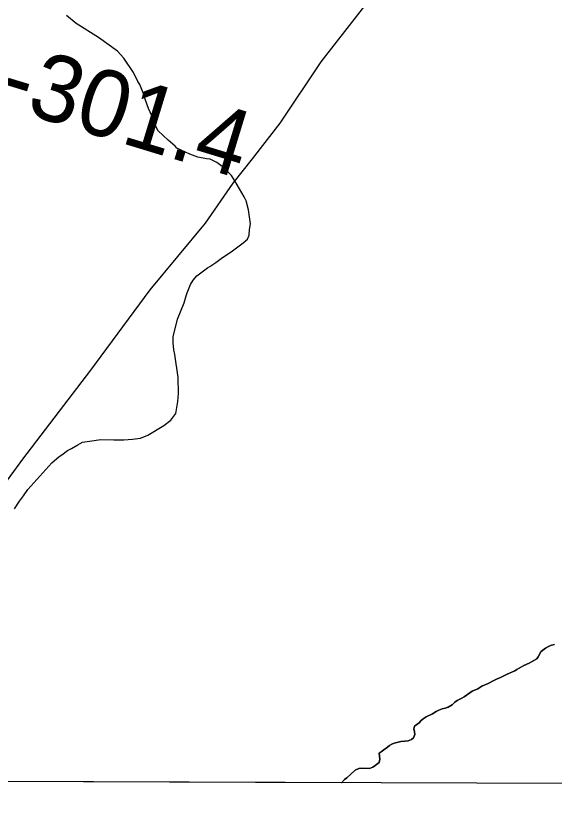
# Model space of a CAD drawing. Extents: x 3146026 to 3183936, y 897894 to 923344.
# Drawn here: x 3175467 to 3176138, y 903274 to 904248 of the extents above; entities that cross this region are included whole.
import ezdxf

# ---------------------------------------------------------------- set-up
doc = ezdxf.new("R2010")
doc.units = 0
for name, color, linetype in [('V-GRID-FRAM', 7, 'Continuous'), ('V-RIVR-RANG-IDEN', 7, 'Continuous'), ('V-ROAD-CNTR', 7, 'Continuous'), ('V-SITE-VEGE', 7, 'Continuous'), ('V-TOPO-SHOR', 7, 'Continuous')]:
    doc.layers.add(name, color=color, linetype=linetype)

msp = doc.modelspace()

# ---------------------------------------------------------------- linework, layer by layer
at = {"layer": 'V-GRID-FRAM'}
msp.add_lwpolyline([(3150311.93, 921563.12), (3181636.98, 921462.88), (3181586.71, 903274.26), (3150245.8, 903374.55), (3150311.93, 921563.12)], dxfattribs=at)
at = {"layer": 'V-ROAD-CNTR'}
msp.add_lwpolyline([(3176191.1, 904677.37), (3176143.65, 904608.46), (3176077.14, 904509.71), (3176012.07, 904414.15), (3175944.13, 904315.76), (3175847.16, 904190.43), (3175795.74, 904114.06), (3175761.27, 904069.68), (3175737.21, 904039.51), (3175703.06, 903989.78), (3175634.13, 903906.72), (3175560.12, 903806.59), (3175475.36, 903695.45), (3175374.76, 903558.74)], dxfattribs=at)
at = {"layer": 'V-SITE-VEGE'}
for p, q in [((3175542.06, 904238.36), (3175530.08, 904248.14)), ((3175570.2, 904221.07), (3175542.06, 904238.36)), ((3175593.71, 904203.82), (3175570.2, 904221.07)), ((3175601.53, 904194.98), (3175593.71, 904203.82)), ((3175613.47, 904177.32), (3175601.53, 904194.98)), ((3175618.97, 904166.18), (3175613.47, 904177.32)), ((3175621.72, 904162.46), (3175618.97, 904166.18)), ((3175625.83, 904151.79), (3175621.72, 904162.46)), ((3175628.56, 904142.98), (3175625.83, 904151.79)), ((3175632.2, 904132.31), (3175628.56, 904142.98)), ((3175636.31, 904123.5), (3175632.2, 904132.31)), ((3175642.25, 904108.19), (3175636.31, 904123.5)), ((3175644.54, 904104.47), (3175642.25, 904108.19)), ((3175656.98, 904092.83), (3175644.54, 904104.47)), ((3175665.73, 904085.37), (3175656.98, 904092.83)), ((3175667.57, 904083.05), (3175665.73, 904085.37)), ((3175683.73, 904075.55), (3175667.57, 904083.05)), ((3175693.89, 904071.8), (3175683.73, 904075.55)), ((3175704.53, 904069.88), (3175693.89, 904071.8)), ((3175709.15, 904069.39), (3175704.53, 904069.88)), ((3175717.46, 904065.18), (3175709.15, 904069.39)), ((3175723.91, 904060.05), (3175717.46, 904065.18)), ((3175735.89, 904048.88), (3175723.91, 904060.05)), ((3175740.02, 904042.37), (3175735.89, 904048.88)), ((3175751.48, 904022.4), (3175740.02, 904042.37)), ((3175753.77, 904017.3), (3175751.48, 904022.4)), ((3175756.94, 904006.17), (3175753.77, 904017.3)), ((3175759.16, 903988.57), (3175756.94, 904006.17)), ((3175757.69, 903974.69), (3175758.2, 903981.63)), ((3175758.2, 903981.63), (3175759.16, 903988.57)), ((3175755.81, 903969.61), (3175757.69, 903974.69)), ((3175735.36, 903953.98), (3175750.23, 903965.01)), ((3175750.23, 903965.01), (3175755.81, 903969.61)), ((3175724.67, 903946.64), (3175735.36, 903953.98)), ((3175716.31, 903940.67), (3175724.67, 903946.64)), ((3175692.61, 903924.13), (3175705.62, 903933.78)), ((3175705.62, 903933.78), (3175708.87, 903935.62)), ((3175708.87, 903935.62), (3175716.31, 903940.67)), ((3175687.95, 903918.61), (3175692.61, 903924.13)), ((3175680.45, 903902.91), (3175684.67, 903913.07)), ((3175684.67, 903913.07), (3175687.95, 903918.61)), ((3175679.04, 903899.21), (3175680.45, 903902.91)), ((3175676.68, 903890.43), (3175679.04, 903899.21)), ((3175668.23, 903870.11), (3175676.68, 903890.43)), ((3175663.02, 903847.92), (3175668.23, 903870.11)), ((3175662.98, 903840.51), (3175663.02, 903847.92)), ((3175663.85, 903831.71), (3175662.98, 903840.51)), ((3175665.21, 903826.15), (3175663.85, 903831.71)), ((3175669.22, 903797.43), (3175665.21, 903826.15)), ((3175669.57, 903777.52), (3175669.22, 903797.43)), ((3175669.05, 903767.34), (3175669.57, 903777.52)), ((3175666.19, 903752.55), (3175669.05, 903767.34)), ((3175660.13, 903744.25), (3175666.19, 903752.55)), ((3175631.32, 903725.43), (3175651.29, 903737.35)), ((3175651.29, 903737.35), (3175660.13, 903744.25)), ((3175550.26, 903716.62), (3175564.55, 903718.92)), ((3175564.55, 903718.92), (3175572.5, 903720.2)), ((3175572.5, 903720.2), (3175589.17, 903719.64)), ((3175589.17, 903719.64), (3175601.66, 903719.57)), ((3175601.66, 903719.57), (3175612.32, 903720.44)), ((3175612.32, 903720.44), (3175622.5, 903721.77)), ((3175622.5, 903721.77), (3175631.32, 903725.43)), ((3175531.23, 903706.54), (3175536.33, 903708.83)), ((3175536.33, 903708.83), (3175544.23, 903713.41)), ((3175544.23, 903713.41), (3175550.26, 903716.62)), ((3175511.7, 903690.91), (3175521, 903698.73)), ((3175521, 903698.73), (3175524.26, 903701.03)), ((3175524.26, 903701.03), (3175531.23, 903706.54)), ((3175481.89, 903657.75), (3175511.7, 903690.91)), ((3175471.63, 903643.46), (3175476.75, 903649.91)), ((3175476.75, 903649.91), (3175481.89, 903657.75)), ((3175465.56, 903633.77), (3175471.63, 903643.46)), ((3176137.86, 903464.72), (3176134.16, 903463.79)), ((3176121.01, 903455.44), (3176117.79, 903449.42)), ((3176123.31, 903457.52), (3176121.01, 903455.44)), ((3176126.77, 903460.07), (3176123.31, 903457.52)), ((3176130.7, 903462.39), (3176126.77, 903460.07)), ((3176134.16, 903463.79), (3176130.7, 903462.39)), ((3176115.94, 903446.64), (3176109.48, 903442.93)), ((3176117.79, 903449.42), (3176115.94, 903446.64)), ((3176099.78, 903438.52), (3176091.24, 903433.42)), ((3176106.48, 903441.31), (3176099.78, 903438.52)), ((3176109.48, 903442.93), (3176106.48, 903441.31)), ((3176079.01, 903427.84), (3176070.01, 903422.97)), ((3176088.48, 903432.02), (3176079.01, 903427.84)), ((3176091.24, 903433.42), (3176088.48, 903432.02)), ((3176055.46, 903416.24), (3176047.61, 903412.75)), ((3176062.62, 903419.95), (3176055.46, 903416.24)), ((3176066.54, 903421.81), (3176062.62, 903419.95)), ((3176070.01, 903422.97), (3176066.54, 903421.81)), ((3176035.38, 903406.49), (3176032.38, 903404.63)), ((3176042.54, 903409.51), (3176035.38, 903406.49)), ((3176047.61, 903412.75), (3176042.54, 903409.51)), ((3176022.69, 903397.68), (3176016.68, 903395.12)), ((3176025.46, 903399.53), (3176022.69, 903397.68)), ((3176032.38, 903404.63), (3176025.46, 903399.53)), ((3176005.61, 903386.78), (3176001.92, 903385.38)), ((3176010.69, 903389.56), (3176005.61, 903386.78)), ((3176013.92, 903393.04), (3176010.69, 903389.56)), ((3176016.68, 903395.12), (3176013.92, 903393.04)), ((3175986.22, 903378.41), (3175978.14, 903374.47)), ((3175990.6, 903381.2), (3175986.22, 903378.41)), ((3175994.06, 903383.05), (3175990.6, 903381.2)), ((3175997.99, 903384.45), (3175994.06, 903383.05)), ((3176001.92, 903385.38), (3175997.99, 903384.45)), ((3175969.6, 903367.28), (3175966.37, 903365.19)), ((3175971.91, 903369.83), (3175969.6, 903367.28)), ((3175974.44, 903372.15), (3175971.91, 903369.83)), ((3175978.14, 903374.47), (3175974.44, 903372.15)), ((3175963.6, 903362.88), (3175962.92, 903359.64)), ((3175962.92, 903359.64), (3175963.85, 903355.95)), ((3175966.37, 903365.19), (3175963.6, 903362.88)), ((3175962.25, 903348.55), (3175959.94, 903346.46)), ((3175964.09, 903352.71), (3175962.25, 903348.55)), ((3175963.85, 903355.95), (3175964.09, 903352.71)), ((3175932.69, 903338.78), (3175930.15, 903336.69)), ((3175935.46, 903340.4), (3175932.69, 903338.78)), ((3175938.23, 903341.79), (3175935.46, 903340.4)), ((3175946.54, 903343.89), (3175938.23, 903341.79)), ((3175951.63, 903344.13), (3175946.54, 903343.89)), ((3175955.79, 903344.61), (3175951.63, 903344.13)), ((3175959.94, 903346.46), (3175955.79, 903344.61)), ((3175922.31, 903330.9), (3175919.77, 903329.27)), ((3175919.77, 903329.27), (3175920.48, 903321.65)), ((3175925.3, 903333.67), (3175922.31, 903330.9)), ((3175930.15, 903336.69), (3175925.3, 903333.67)), ((3175920.48, 903321.65), (3175919.56, 903317.72)), ((3175894.39, 903310.27), (3175889.77, 903308.18)), ((3175897.39, 903310.5), (3175894.39, 903310.27)), ((3175907.56, 903310.3), (3175897.39, 903310.5)), ((3175911.95, 903311.92), (3175907.56, 903310.3)), ((3175914.72, 903313.78), (3175911.95, 903311.92)), ((3175919.56, 903317.72), (3175914.72, 903313.78)), ((3175889.77, 903308.18), (3175879.16, 903298.68)), ((3175872.59, 903292.54), (3175403.51, 903294.04)), ((3175876.62, 903296.59), (3175872.59, 903292.54)), ((3175879.16, 903298.68), (3175876.62, 903296.59))]:
    msp.add_line(p, q, dxfattribs=at)
at = {"layer": 'V-TOPO-SHOR'}
for points in [[(3175930.15, 903336.69), (3175932.69, 903338.78), (3175935.46, 903340.4), (3175938.23, 903341.79), (3175946.54, 903343.89), (3175951.63, 903344.13), (3175955.79, 903344.61), (3175959.94, 903346.46), (3175962.25, 903348.55), (3175964.09, 903352.71), (3175963.85, 903355.95), (3175962.92, 903359.64), (3175963.6, 903362.88), (3175966.37, 903365.2), (3175969.6, 903367.28), (3175971.91, 903369.83), (3175974.44, 903372.15), (3175978.14, 903374.47), (3175986.22, 903378.41), (3175990.6, 903381.2), (3175994.06, 903383.05), (3175997.99, 903384.45), (3176001.92, 903385.38), (3176005.61, 903386.78), (3176010.69, 903389.56), (3176013.92, 903393.04), (3176016.68, 903395.12), (3176022.69, 903397.68), (3176025.46, 903399.53), (3176032.38, 903404.63), (3176035.38, 903406.49), (3176042.54, 903409.51), (3176047.61, 903412.75), (3176055.46, 903416.24), (3176062.62, 903419.95), (3176066.54, 903421.81), (3176070.01, 903422.97), (3176079.01, 903427.84), (3176088.48, 903432.02), (3176091.24, 903433.42), (3176099.78, 903438.52), (3176106.48, 903441.31), (3176109.48, 903442.93), (3176115.94, 903446.64), (3176117.79, 903449.42), (3176121.01, 903455.44), (3176123.31, 903457.52), (3176126.77, 903460.07), (3176130.7, 903462.39), (3176134.16, 903463.79), (3176137.86, 903464.72)], [(3175872.59, 903292.54), (3175876.62, 903296.59), (3175879.16, 903298.68), (3175889.77, 903308.18), (3175894.39, 903310.27), (3175897.39, 903310.5), (3175907.56, 903310.3), (3175911.95, 903311.92), (3175914.72, 903313.78), (3175919.56, 903317.72), (3175920.48, 903321.65), (3175919.77, 903329.27), (3175922.31, 903330.9), (3175925.3, 903333.68), (3175930.15, 903336.69)]]:
    msp.add_lwpolyline(points, dxfattribs=at)

# ---------------------------------------------------------------- texts
at = {"layer": 'V-RIVR-RANG-IDEN'}
msp.add_text('R-301.4', height=83, rotation=343.04236, dxfattribs=at).set_placement((3175365.74, 904160.42))

doc.saveas('drawing.dxf')
